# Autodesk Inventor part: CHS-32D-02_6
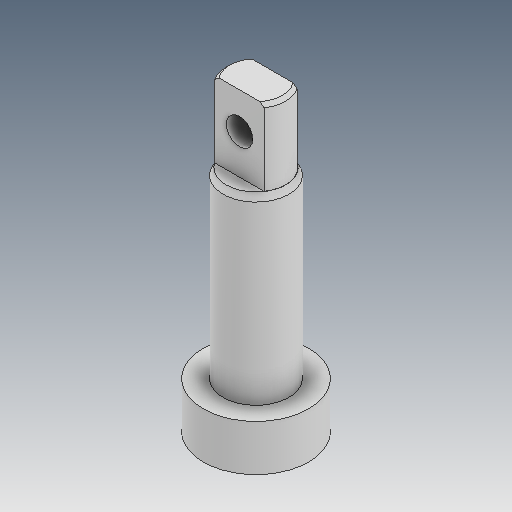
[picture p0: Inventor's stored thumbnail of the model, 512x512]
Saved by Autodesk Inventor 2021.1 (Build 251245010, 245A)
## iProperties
Created: 2021-05
Part Number: CHS-32D-02_6
Material: Ogólny
Document SubType Name: Modeling
Designer: user
Density: 1 g/cm^3
Appearance: Domyślna
Author: user
Revision Number: ÈÎºÎ
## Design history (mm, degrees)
feature "ÊäÈë1"
feature "ÊäÈë2"
node "Bryła1"
node "Bryła2"
